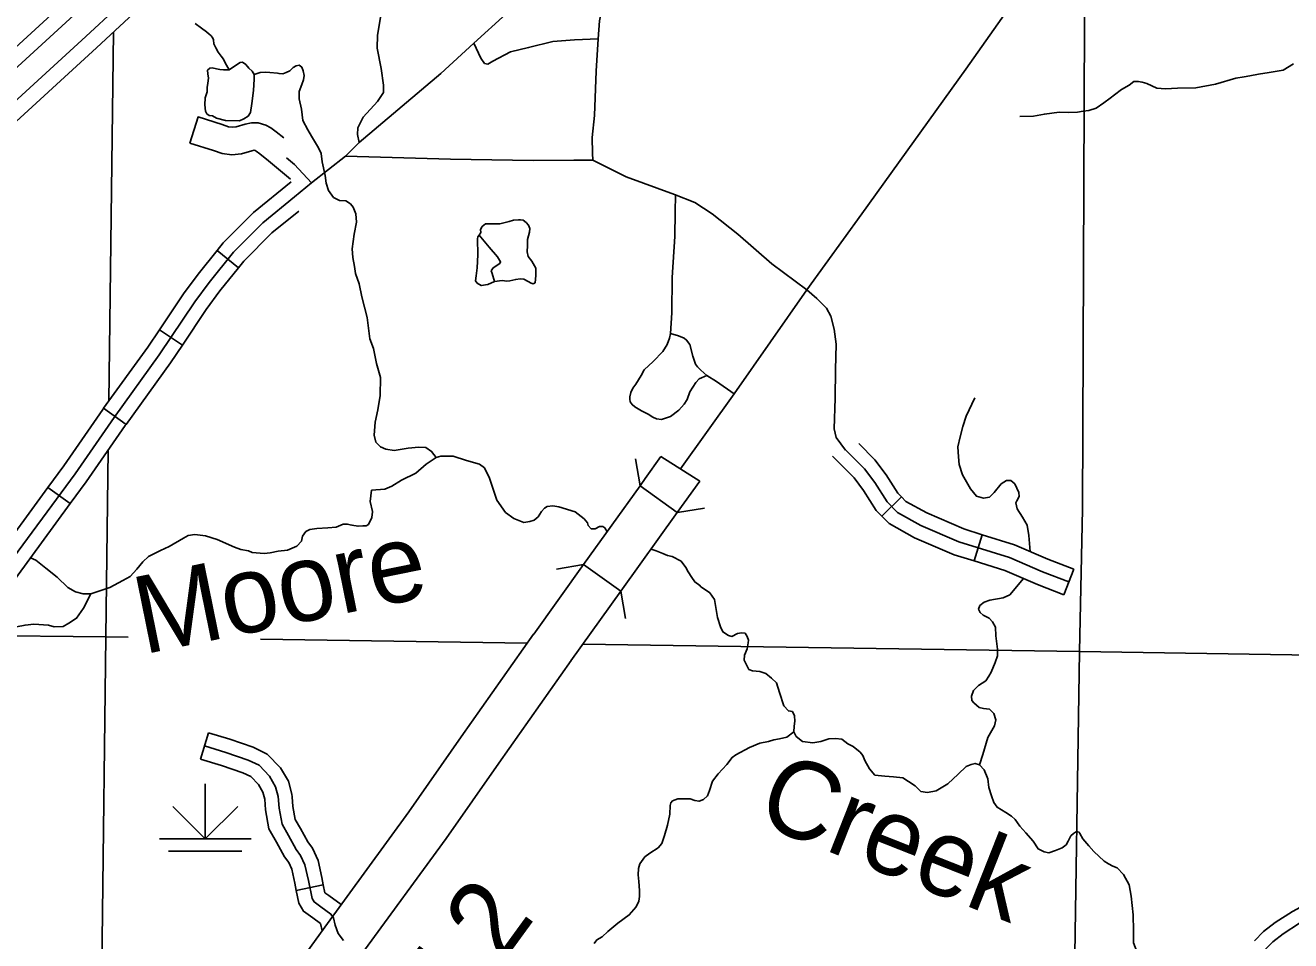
# Model space of a CAD drawing. Extents: x 8749 to 11879, y 13275 to 15339.
# Drawn here: x 9983.2 to 10121.1, y 13518.3 to 13618.1 of the extents above; entities that cross this region are included whole.
import ezdxf

# ---------------------------------------------------------------- set-up
doc = ezdxf.new("R2010")
doc.units = 0
for name, color, linetype in [('Level 15', 7, 'Continuous'), ('Level 19', 7, 'Continuous'), ('Level 32', 7, 'Continuous'), ('Level 35', 7, 'Continuous'), ('Level 37', 7, 'Continuous'), ('Level 44', 7, 'Continuous'), ('Level 45', 7, 'Continuous'), ('Level 46', 7, 'Continuous'), ('Level 48', 7, 'Continuous'), ('Level 5', 7, 'Continuous')]:
    doc.layers.add(name, color=color, linetype=linetype)

msp = doc.modelspace()

# ---------------------------------------------------------------- linework, layer by layer
at = {"layer": 'Level 15'}
msp.add_line((10056.71, 13568.38), (10052.47, 13571.05), dxfattribs=at)
for points in [[(10094.19, 13625.31), (10085.73, 13613.29), (10074.39, 13597.53), (10068.37, 13589.22), (10060.47, 13577.91), (10054.59, 13569.72)], [(9992.83, 13575.32), (9997.76, 13582.15), (10001.65, 13587.94), (10003.19, 13590.03), (10005.86, 13593.36), (10009.05, 13596.55), (10012.52, 13599.39)], [(9975.1, 13550.58), (9980.85, 13558.65), (9988.59, 13569.18), (9992.83, 13575.32)], [(10052.47, 13571.05), (10050.76, 13568.66), (10050.19, 13567.87)], [(10050.19, 13567.87), (10044.04, 13559.28)], [(10050.19, 13567.87), (10054.25, 13564.95)], [(10054.25, 13564.95), (10055.01, 13566.01), (10056.71, 13568.38)], [(10054.25, 13564.95), (10048.1, 13556.37)], [(10038.59, 13551.7), (10044.04, 13559.28)], [(10044.04, 13559.28), (10048.1, 13556.37)], [(10048.1, 13556.37), (10042.66, 13548.78)], [(9962.47, 13445.33), (9970.38, 13456.2), (9982.57, 13473.43), (9990.59, 13484.49), (9999.86, 13497.38), (10005.27, 13505.12), (10015.82, 13519.75), (10024.97, 13532.31), (10030.69, 13540.5), (10038.58, 13551.68)], [(9966.51, 13442.39), (9974.44, 13453.28), (9986.63, 13470.52), (9994.64, 13481.56), (10003.94, 13494.48), (10009.35, 13502.22), (10019.87, 13516.82), (10029.04, 13529.41), (10034.79, 13537.62), (10042.67, 13548.8)]]:
    msp.add_lwpolyline(points, dxfattribs=at)
at = {"layer": 'Level 19'}
for points in [[(9996.99, 13629.44), (9986.85, 13620.03), (9964.99, 13600.02), (9954.18, 13590.48), (9938.87, 13577.88), (9926.88, 13568.51), (9905.66, 13552.12), (9898.16, 13546.32), (9886.51, 13537.43), (9886.51, 13535.29)], [(9886.51, 13535.29), (9899.2, 13544.97), (9906.7, 13550.77), (9927.92, 13567.17), (9939.93, 13576.55), (9955.28, 13589.19), (9966.13, 13598.75), (9988, 13618.78), (9998.09, 13628.1)], [(9999.89, 13626.27), (9989.76, 13616.86), (9967.87, 13596.82), (9956.97, 13587.21), (9941.56, 13574.52), (9929.52, 13565.11), (9908.29, 13548.72), (9900.79, 13542.91), (9886.98, 13532.37)], [(9888.01, 13531.02), (9901.82, 13541.56), (9909.33, 13547.37), (9930.56, 13563.77), (9942.62, 13573.2), (9958.07, 13585.92), (9969, 13595.56), (9990.91, 13615.61), (10001.04, 13625.02)]]:
    msp.add_lwpolyline(points, dxfattribs=at)
at = {"layer": 'Level 32'}
for p, q in [((10006.41, 13591.65), (10004.06, 13593.52)), ((10000.28, 13583.21), (9997.79, 13584.88)), ((9994.14, 13574.56), (9991.7, 13576.32)), ((9988.05, 13565.92), (9985.63, 13567.69)), ((10078.69, 13566.65), (10076.54, 13564.57)), ((10087.51, 13562.53), (10086.62, 13559.67)), ((10097.48, 13558.79), (10096.4, 13555.99))]:
    msp.add_line(p, q, dxfattribs=at)
for points in [[(10032.08, 13616.12), (10035.59, 13619.32), (10038.64, 13621.69), (10041.86, 13624.58), (10046.36, 13628.25)], [(10045.04, 13603.37), (10045, 13604.12), (10044.98, 13605.84), (10045.21, 13608.25), (10045.42, 13613.07), (10045.63, 13616.6), (10045.78, 13618.55), (10046.07, 13619.95), (10046.53, 13621), (10047.66, 13622.57), (10047.91, 13622.98), (10047.95, 13623.59), (10047.89, 13624.68), (10047.64, 13625.91), (10047.1, 13627.25), (10046.36, 13628.25)], [(10018.06, 13603.81), (10019.55, 13605.31), (10028.45, 13612.83), (10032.08, 13616.12)], [(10032.08, 13616.12), (10032.82, 13614.48), (10033.24, 13613.93), (10033.6, 13613.85), (10034.13, 13614.18), (10036.06, 13615.17), (10038.03, 13615.65), (10040.69, 13616.3), (10043.04, 13616.51), (10045.63, 13616.6)], [(10012.52, 13599.39), (10014.37, 13600.9), (10018.06, 13603.81)], [(10068.37, 13589.22), (10064.57, 13592.08), (10060.87, 13595.31), (10058.05, 13597.54), (10056.15, 13598.75), (10053.94, 13599.63), (10048.66, 13601.57), (10045.04, 13603.37), (10042.98, 13603.37), (10038.53, 13603.34), (10029.53, 13603.48), (10018.06, 13603.81)], [(10004.06, 13593.52), (10004.74, 13594.37), (10008.04, 13597.67), (10012.13, 13601)], [(10053.5, 13584.47), (10053.67, 13586.72), (10053.69, 13590.57), (10053.99, 13595.04), (10054.01, 13597.72), (10054.05, 13599.58)], [(10006.41, 13591.65), (10006.98, 13592.36), (10010.05, 13595.44), (10012.97, 13597.82)], [(9997.79, 13584.88), (10000.42, 13588.8), (10002, 13590.94), (10004.06, 13593.52)], [(10000.28, 13583.21), (10002.88, 13587.08), (10004.38, 13589.11), (10006.41, 13591.65)], [(10071.46, 13577.43), (10071.5, 13580.51), (10071.56, 13583.31), (10071.35, 13584.93), (10071, 13586.35), (10070.52, 13587.23), (10069.47, 13588.3), (10068.37, 13589.22)], [(9991.7, 13576.32), (9996.53, 13583), (9997.79, 13584.88)], [(10057.46, 13579.88), (10056.65, 13579.54), (10056.27, 13579.12), (10055.62, 13578.12), (10055.32, 13577.26), (10055.01, 13576.76), (10054.42, 13576.13), (10053.5, 13575.42), (10052.52, 13575.11), (10051.98, 13575.15), (10051.6, 13575.36), (10051.08, 13575.69), (10050.36, 13576.03), (10049.61, 13576.47), (10049.32, 13576.72), (10049.13, 13577.03), (10049.07, 13577.33), (10049.07, 13577.58), (10049.17, 13578.04), (10049.42, 13578.52), (10049.74, 13578.94), (10050.3, 13579.9), (10050.64, 13580.51), (10051.62, 13581.41), (10052.69, 13582.5), (10053.15, 13583.28), (10053.4, 13583.97), (10053.5, 13584.47)], [(10060.47, 13577.91), (10058.54, 13579.25), (10057.46, 13579.88), (10056.81, 13580.49), (10056.45, 13580.83), (10056.24, 13581.14), (10055.93, 13582), (10055.61, 13583.26), (10055.26, 13583.76), (10055.01, 13583.95), (10054.4, 13584.22), (10053.5, 13584.47)], [(9994.14, 13574.56), (9999, 13581.29), (10000.28, 13583.21)], [(10071.46, 13577.43), (10071.37, 13574.07), (10071.56, 13573.12), (10072.61, 13571.76)], [(9985.63, 13567.69), (9987.37, 13570.05), (9991.61, 13576.19), (9991.7, 13576.32)], [(9988.05, 13565.92), (9989.81, 13568.31), (9994.06, 13574.45), (9994.14, 13574.56)], [(10078.69, 13566.65), (10078.31, 13567.05), (10077.04, 13569.06), (10075.81, 13570.7), (10074.03, 13572.48)], [(10076.54, 13564.57), (10075.94, 13565.19), (10074.57, 13567.35), (10073.54, 13568.72), (10071.17, 13571.1)], [(10096.94, 13557.39), (10094.08, 13558.49), (10090.49, 13560.03), (10084.96, 13561.75), (10080.79, 13563.55), (10078.26, 13564.94), (10077.13, 13566.12), (10075.81, 13568.21), (10074.67, 13569.71), (10072.62, 13571.76)], [(9979.37, 13559.16), (9979.64, 13559.53), (9985.63, 13567.69)], [(10087.51, 13562.53), (10085.48, 13563.16), (10081.45, 13564.9), (10079.18, 13566.15), (10078.69, 13566.65)], [(9981.82, 13557.42), (9982.07, 13557.77), (9988.05, 13565.92)], [(10086.62, 13559.67), (10084.44, 13560.35), (10080.13, 13562.2), (10077.34, 13563.74), (10076.54, 13564.57)], [(10097.48, 13558.79), (10094.65, 13559.88), (10091.02, 13561.44), (10087.51, 13562.53)], [(10096.4, 13555.99), (10093.52, 13557.1), (10089.97, 13558.62), (10086.62, 13559.67)], [(10126.39, 13524.18), (10125.74, 13523.81), (10123.07, 13522.39), (10121.33, 13521.46), (10119.44, 13520.23), (10118.19, 13519.26), (10117.21, 13518.26)]]:
    msp.add_lwpolyline(points, dxfattribs=at)
at = {"layer": 'Level 35'}
for points in [[(10005.4, 13613.22), (10005.1, 13613.73), (10004.92, 13614.07), (10004.78, 13614.39), (10004.52, 13614.71), (10004.17, 13615.16), (10003.95, 13615.61), (10003.7, 13616.07), (10003.67, 13616.5), (10003.56, 13616.76), (10003.38, 13616.95), (10003.19, 13617.13), (10002.9, 13617.36), (10002.36, 13617.78), (10001.69, 13618.28)], [(10004, 13607.95), (10004.98, 13607.71), (10006.53, 13607.67), (10007, 13607.87), (10007.47, 13608.18), (10007.72, 13608.57), (10007.87, 13609.55), (10008.04, 13610.98), (10008.13, 13612.19), (10008.11, 13612.73), (10007.9, 13613.07), (10007.53, 13613.42), (10007.2, 13613.81), (10006.85, 13614.07), (10006.57, 13614.02), (10005.96, 13613.62), (10005.4, 13613.22), (10004.76, 13613.21), (10004.37, 13613.27), (10003.99, 13613.34), (10003.52, 13613.44), (10003.28, 13613.39), (10003.03, 13613.17), (10003.05, 13612.79), (10003.14, 13612.31), (10003.06, 13611.76), (10002.98, 13611.28), (10002.98, 13610.82), (10002.78, 13610.17), (10002.75, 13609.4), (10002.82, 13608.73), (10002.94, 13608.44), (10003.22, 13608.24), (10003.56, 13608.22), (10004, 13607.95)], [(10013.3, 13613.53), (10013.02, 13613.73), (10012.71, 13613.67), (10012.37, 13613.47), (10012, 13613.13), (10011.6, 13612.93), (10011.25, 13612.79), (10010.83, 13612.82), (10010.65, 13612.87), (10009.83, 13612.95), (10009.38, 13612.98), (10008.78, 13612.92), (10008.11, 13612.73)], [(10027.96, 13570.94), (10027.46, 13571.62), (10026.84, 13572.03), (10026.05, 13572.08), (10024.92, 13571.97), (10023.39, 13571.73), (10022.47, 13571.87), (10021.9, 13572.11), (10021.39, 13572.62), (10021.2, 13573.38), (10021.31, 13574.81), (10021.58, 13576.16), (10021.85, 13577.7), (10021.88, 13579.67), (10021.44, 13581.21), (10021.12, 13582.83), (10020.72, 13583.89), (10020.42, 13586.23), (10019.85, 13588.47), (10019.58, 13589.9), (10019.18, 13591.02), (10019.05, 13591.78), (10018.88, 13592.75), (10018.8, 13593.72), (10019.02, 13595.29), (10019.26, 13596.61), (10019.21, 13597.53), (10018.91, 13598.26), (10018.61, 13598.63), (10018.1, 13598.93), (10017.4, 13598.99), (10016.78, 13599.32), (10016.22, 13600.07), (10015.95, 13600.86), (10015.84, 13601.72), (10015.54, 13603.2), (10015.43, 13604.1), (10015.11, 13604.72), (10014.36, 13605.98), (10013.95, 13606.69), (10013.41, 13607.71), (10013.28, 13608.95), (10013.01, 13610.06), (10013.01, 13610.86), (10013.3, 13611.64), (10013.49, 13612.15), (10013.55, 13612.61), (10013.47, 13613.12), (10013.3, 13613.53)], [(10110.79, 13611.26), (10112.93, 13611.67), (10115.14, 13612.31), (10116.05, 13612.45), (10116.7, 13612.58), (10117.64, 13612.75), (10118.78, 13612.93), (10120.31, 13613.2), (10121.44, 13613.88)], [(10091.6, 13608.13), (10093.11, 13608.18), (10094.29, 13608.4), (10095.91, 13608.59), (10096.91, 13608.56), (10097.9, 13608.62), (10098.5, 13608.7), (10099.12, 13608.78), (10099.93, 13609.05), (10100.76, 13609.64), (10101.44, 13610.15), (10101.92, 13610.51), (10102.7, 13611.07), (10103.54, 13611.56), (10104.05, 13611.94), (10104.51, 13611.96), (10104.94, 13611.88), (10105.45, 13611.72), (10106.56, 13611.23), (10107.5, 13611.15), (10108.79, 13611.21), (10110.79, 13611.26)], [(10032.48, 13594.8), (10032.5, 13595.01), (10032.65, 13595.18), (10032.84, 13595.47), (10032.79, 13595.81), (10032.96, 13596.13), (10033.34, 13596.42), (10033.68, 13596.44), (10034.18, 13596.42), (10034.89, 13596.44), (10035.92, 13596.69), (10036.38, 13596.84), (10036.95, 13596.86), (10037.16, 13596.86), (10037.43, 13596.82), (10037.77, 13596.59), (10038.04, 13596.29), (10038.17, 13595.92), (10038.12, 13595.54), (10037.91, 13594.74), (10037.91, 13594.07), (10037.89, 13593.37), (10037.98, 13592.87), (10038.38, 13592.37), (10038.82, 13591.61), (10038.82, 13590.79), (10038.75, 13590.01), (10038.54, 13589.89), (10038.31, 13589.97), (10037.98, 13590.16), (10037.52, 13590.39), (10037.1, 13590.43), (10036.63, 13590.37), (10036, 13590.22), (10035.65, 13590.18), (10035.17, 13590.24), (10034.31, 13590.16)], [(10032.48, 13594.8), (10032.5, 13593.06), (10032.44, 13591.65), (10032.33, 13590.75), (10032.25, 13590.22), (10032.42, 13589.97), (10032.88, 13589.7), (10033.59, 13589.82), (10034.31, 13590.16)], [(10032.65, 13595.18), (10033.74, 13593.9), (10034.66, 13592.83), (10034.98, 13592.3), (10034.89, 13592.11), (10034.18, 13591.63), (10033.97, 13591.32), (10034.05, 13591), (10034.31, 13590.16)], [(10092.72, 13560.71), (10092.57, 13562.46), (10092.39, 13563.59), (10091.9, 13564.45), (10091.33, 13565.37), (10091.17, 13566.02), (10091.28, 13566.24), (10091.52, 13566.69), (10091.5, 13567.13), (10091.04, 13568.07), (10090.61, 13568.45), (10090.15, 13568.45), (10089.58, 13568.07), (10088.8, 13567.15), (10088.29, 13566.61), (10087.64, 13566.53), (10086.86, 13566.75), (10086.21, 13567.53), (10085.35, 13569.07), (10085, 13570.2), (10084.92, 13571.03), (10084.84, 13572.13), (10085.11, 13573.21), (10085.4, 13574.32), (10085.75, 13575.45), (10086.7, 13577.45)], [(10020.9, 13567.39), (10022.35, 13567.49), (10023.14, 13567.84), (10024.16, 13568.49), (10025.75, 13569.24), (10026.88, 13570.22), (10027.96, 13570.94), (10028.47, 13571.08), (10028.98, 13571.11), (10029.82, 13571.08), (10031.28, 13570.62), (10032.68, 13570.24), (10033.24, 13569.82), (10033.78, 13568.69), (10034.59, 13566.31), (10035.53, 13564.96), (10036.42, 13564.29), (10037.5, 13563.86), (10038.17, 13563.96), (10038.63, 13564.13), (10039.08, 13564.49), (10039.46, 13565.05), (10039.76, 13565.43), (10040.06, 13565.61), (10040.68, 13565.69), (10041.35, 13565.58), (10043.1, 13565.02), (10044.1, 13564.26), (10044.45, 13563.81), (10044.55, 13563.52), (10044.85, 13563.19), (10045.31, 13563.17), (10045.77, 13563.43), (10046.14, 13563.41), (10046.36, 13563.27), (10046.59, 13562.84)], [(10020.57, 13563.66), (10020.93, 13564.4), (10021.03, 13565.04), (10021.03, 13565.07), (10020.76, 13566.15), (10020.9, 13567.39)], [(10016.16, 13563.27), (10017.04, 13563.37), (10017.8, 13563.67), (10018.26, 13563.69), (10018.77, 13563.59), (10019.44, 13563.45), (10019.95, 13563.5), (10020.33, 13563.5), (10020.57, 13563.66)], [(9993.79, 13557.55), (9994.6, 13557.98), (9995.3, 13558.79), (9995.98, 13559.58), (9996.6, 13560.14), (9997.89, 13560.82), (9998.83, 13561.25), (10000.42, 13562.17), (10000.91, 13562.44), (10001.66, 13562.54), (10002.82, 13562.41), (10004.06, 13562), (10005.95, 13561.17), (10006.65, 13560.93), (10007.49, 13560.79), (10007.91, 13560.6), (10009.21, 13560.49), (10009.85, 13560.57), (10010.74, 13560.74), (10011.74, 13560.84), (10012.76, 13561.28), (10013.28, 13561.84), (10013.38, 13562.38), (10013.73, 13562.87), (10014.19, 13563.11), (10014.95, 13563.22), (10016.16, 13563.27)], [(10062.07, 13547.84), (10061.53, 13548.86), (10061.59, 13549.4), (10061.88, 13550.1), (10061.99, 13550.73), (10062.02, 13551.05), (10061.86, 13551.45), (10061.64, 13551.78), (10061.26, 13551.83), (10060.81, 13551.75), (10060.19, 13551.45), (10059.84, 13551.56), (10059.22, 13551.94), (10058.95, 13552.48), (10058.65, 13553.5), (10058.46, 13554.58), (10058.3, 13555.45), (10057.81, 13556.18), (10057.33, 13556.53), (10056.82, 13556.85), (10056.71, 13557.01), (10056.17, 13557.39), (10055.85, 13557.88), (10055.44, 13558.5), (10055.17, 13558.96), (10054.66, 13559.66), (10053.69, 13560.14), (10053.2, 13560.25), (10052.67, 13560.47), (10051.96, 13560.79), (10051.39, 13560.97)], [(9984.3, 13559.77), (9983.71, 13560.01)], [(9993.79, 13557.55), (9992.36, 13556.77), (9991.17, 13556.39), (9990.31, 13556.07), (9989.47, 13556.1), (9988.64, 13556.29), (9987.8, 13556.77), (9986.62, 13557.9), (9985.4, 13558.88), (9984.3, 13559.77)], [(10090.5, 13555.96), (10091.99, 13557.76)], [(9979.21, 13549.09), (9979.91, 13550.44), (9981.18, 13551.68), (9982.2, 13552.49), (9983.14, 13552.68), (9984.09, 13552.76), (9985.68, 13552.68), (9986.3, 13552.49), (9987.29, 13552.54), (9987.91, 13552.87), (9988.75, 13553.43), (9989.5, 13554.54), (9990.31, 13556.07)], [(10087.19, 13537.43), (10087.56, 13538.58), (10088.13, 13540.42), (10088.83, 13541.69), (10088.99, 13542.36), (10088.77, 13543.04), (10088.29, 13543.5), (10087.64, 13543.6), (10087.18, 13543.68), (10086.59, 13544.2), (10086.37, 13544.47), (10086.32, 13544.94), (10086.54, 13545.56), (10087.08, 13546.1), (10087.91, 13546.61), (10088.23, 13547.12), (10088.48, 13547.55), (10088.91, 13548.58), (10089.15, 13549.31), (10089.18, 13550.06), (10088.99, 13551.52), (10088.94, 13552.44), (10088.64, 13553.05), (10088.26, 13553.45), (10087.61, 13553.75), (10087.26, 13554.05), (10087.1, 13554.42), (10087.24, 13554.8), (10087.7, 13555.18), (10088.34, 13555.4), (10089.8, 13555.64), (10090.5, 13555.96)], [(10062.07, 13547.84), (10062.46, 13547.69), (10063.27, 13547.63), (10063.92, 13547.39), (10064.54, 13546.88), (10065.08, 13546.39), (10065.4, 13545.31), (10065.88, 13543.88), (10066.37, 13543.32), (10066.8, 13543.26), (10067.02, 13542.8), (10067.07, 13542.21), (10066.99, 13541.64), (10066.96, 13541.05), (10067.23, 13540.54), (10067.91, 13540), (10069.04, 13539.83), (10069.9, 13539.97)], [(10066.96, 13541.05), (10066.19, 13540.46), (10065.38, 13540.28), (10064.79, 13540.17), (10064.19, 13539.98), (10063.25, 13539.79), (10062.12, 13539.33), (10060.63, 13538.52), (10060.23, 13538.25), (10059.64, 13537.47), (10058.72, 13536.44), (10058.1, 13535.66), (10057.75, 13534.63), (10057.53, 13534.07), (10057.1, 13533.66), (10056.62, 13533.47), (10056.16, 13533.55), (10055.67, 13533.72), (10055.11, 13533.74), (10054.32, 13533.74), (10053.73, 13533.5), (10053.54, 13533.28), (10053.49, 13532.99)], [(10069.9, 13539.97), (10070.77, 13540.26), (10071.5, 13540.32), (10072.2, 13540.24), (10072.85, 13539.72), (10073.44, 13539.43), (10074.2, 13538.81), (10074.47, 13538.46), (10074.71, 13537.92), (10075.22, 13537), (10075.81, 13536.32), (10076.89, 13536.19), (10077.81, 13536.14), (10078.83, 13536.03), (10079.48, 13535.62), (10080.18, 13535.16), (10080.8, 13534.54), (10081.55, 13534.44), (10082.47, 13534.62), (10083.74, 13535.38), (10084.87, 13536.41), (10085.76, 13537.24), (10086.3, 13537.48), (10086.73, 13537.59), (10087.19, 13537.43), (10087.72, 13536.89), (10088.13, 13535.92), (10088.23, 13534.98), (10088.5, 13534.06), (10088.75, 13533.33), (10089.12, 13532.82), (10090.07, 13532.25), (10090.71, 13531.84), (10091.09, 13531.49), (10091.6, 13530.74), (10092.25, 13530.04), (10093.06, 13529.13), (10093.6, 13528.29), (10094.24, 13527.97), (10094.76, 13527.86), (10095.48, 13528.08), (10096.21, 13528.4), (10096.64, 13528.7), (10096.89, 13529.13), (10097.18, 13529.69), (10097.45, 13529.96), (10097.78, 13530.18), (10098.07, 13530.1), (10098.15, 13529.94), (10098.48, 13529.37), (10099.12, 13528.61), (10099.69, 13527.99)], [(10053.49, 13532.99), (10053.44, 13532.06), (10053.17, 13530.87), (10052.87, 13529.74), (10052.58, 13528.87), (10052.17, 13528.39), (10051.25, 13527.79), (10050.72, 13527.39), (10050.15, 13526.66), (10050.01, 13526.12), (10049.99, 13525.45), (10050.07, 13524.72), (10050.12, 13523.72), (10050.12, 13523.07), (10050.07, 13522.58), (10049.77, 13521.96), (10049.02, 13521.07), (10047.75, 13520.16)], [(10106.77, 13512.25), (10105.81, 13513.11), (10105.22, 13514.41), (10105.01, 13515.81), (10104.44, 13516.92), (10104.01, 13518.02), (10103.98, 13519.32), (10103.95, 13521.1), (10103.74, 13523.1), (10103.52, 13524.37), (10102.9, 13525.49), (10102.23, 13526.19), (10101.74, 13526.4), (10101.26, 13526.65), (10100.8, 13526.94), (10099.69, 13527.99)], [(10045.19, 13517.95), (10045.49, 13518.36), (10046.05, 13518.68), (10046.67, 13519.25), (10047.75, 13520.16)]]:
    msp.add_lwpolyline(points, dxfattribs=at)
at = {"layer": 'Level 37'}
for points in [[(10050.19, 13567.86), (10049.7, 13570.82)], [(10057.22, 13565.44), (10054.26, 13564.95)], [(10041.08, 13558.79), (10044.04, 13559.28)], [(10048.11, 13556.37), (10048.59, 13553.41)]]:
    msp.add_lwpolyline(points, dxfattribs=at)
at = {"layer": 'Level 44'}
for p, q in [((10002.78, 13535.38), (10002.78, 13529.38)), ((10002.78, 13529.38), (9999.25, 13532.91)), ((10002.78, 13529.38), (10006.32, 13532.91)), ((9997.78, 13529.38), (10007.78, 13529.38)), ((9998.78, 13528.01), (10006.78, 13528.01))]:
    msp.add_line(p, q, dxfattribs=at)
at = {"layer": 'Level 45'}
for p, q in [((10002.25, 13538.06), (10003.12, 13540.93)), ((10012.71, 13523.73), (10015.65, 13524.34))]:
    msp.add_line(p, q, dxfattribs=at)
for points in [[(10019.55, 13605.31), (10019.37, 13606.19), (10019.41, 13606.89), (10019.99, 13608.06), (10021.57, 13609.78), (10022.23, 13610.77), (10022.23, 13611.54), (10021.97, 13613.38), (10021.53, 13615.58), (10021.57, 13617.01), (10022.23, 13620.89), (10022.48, 13622.32), (10023.29, 13623.68), (10025.12, 13625.62), (10026.8, 13626.98), (10027.27, 13627.48), (10027.9, 13628.22), (10028.44, 13627.87)], [(10003.12, 13540.93), (10005.47, 13540.22), (10008.02, 13539.36), (10009.54, 13538.62), (10010.99, 13537.12), (10011.84, 13535.64), (10012.22, 13534.25), (10012.25, 13533.96)], [(10002.68, 13539.5), (10005.01, 13538.79), (10007.45, 13537.96), (10008.65, 13537.39), (10009.78, 13536.21), (10010.44, 13535.05), (10010.74, 13533.98), (10010.85, 13532.72), (10011.15, 13530.96), (10011.85, 13529.74), (10012.69, 13528.22), (10013.18, 13527.57), (10013.65, 13526.52), (10014.02, 13524.83), (10014.42, 13522.88), (10014.64, 13522.5), (10015.38, 13521.96), (10016.48, 13521.17), (10016.75, 13520.76), (10016.93, 13519.95), (10017.29, 13519.03), (10017.85, 13518.29)], [(10002.25, 13538.06), (10004.56, 13537.36), (10006.88, 13536.57), (10007.75, 13536.15), (10008.57, 13535.3), (10009.05, 13534.47), (10009.26, 13533.71), (10009.26, 13533.71)], [(10009.26, 13533.71), (10009.36, 13532.53), (10009.72, 13530.45), (10010.55, 13529.01), (10011.43, 13527.4), (10011.88, 13526.8), (10012.22, 13526.05), (10012.55, 13524.52), (10012.71, 13523.73)], [(10012.25, 13533.96), (10012.34, 13532.91), (10012.58, 13531.48), (10013.16, 13530.48), (10013.95, 13529.04), (10014.48, 13528.35), (10015.09, 13526.99), (10015.48, 13525.14), (10015.65, 13524.34)], [(10012.71, 13523.73), (10013, 13522.36), (10013.49, 13521.48), (10014.51, 13520.75), (10015.35, 13520.13), (10015.52, 13519.34)], [(10015.65, 13524.34), (10015.83, 13523.49), (10016.26, 13523.18), (10017.61, 13522.2)]]:
    msp.add_lwpolyline(points, dxfattribs=at)
at = {"layer": 'Level 46'}
for points in [[(10011.33, 13605.82), (10010.52, 13606.48), (10009.94, 13606.89), (10009.4, 13607.19), (10008.55, 13607.45), (10007.83, 13607.45), (10007.12, 13607.3), (10006.14, 13607.01), (10005.71, 13606.96), (10005.33, 13607.02), (10004.61, 13607.27), (10001.99, 13608.09), (10001.09, 13605.23)], [(10001.09, 13605.23), (10003.66, 13604.42), (10004.61, 13604.09), (10005.66, 13603.94), (10006.74, 13604.06), (10007.85, 13604.39), (10008.12, 13604.45), (10008.21, 13604.42), (10008.34, 13604.34), (10008.72, 13604.08), (10009.69, 13603.29), (10012.06, 13601.32)], [(10014.37, 13600.9), (10012.51, 13602.89), (10011.62, 13603.63)], [(10163.26, 13544.72), (10161.96, 13544), (10151.35, 13537.91), (10146.61, 13535.22), (10142.06, 13532.33), (10133.23, 13526.58), (10129.49, 13524.21), (10126.46, 13522.49), (10123.78, 13521.07), (10122.09, 13520.16), (10120.31, 13519.01), (10119.19, 13518.13), (10117.16, 13516.07), (10115.66, 13514.6), (10114.8, 13513.81), (10113.83, 13513.12), (10112.83, 13512.65)]]:
    msp.add_lwpolyline(points, dxfattribs=at)
at = {"layer": 'Level 5'}
for points in [[(10098.69, 13627.31), (10098.42, 13565.32), (10098.11, 13549.79)], [(9992.76, 13617.33), (9992.27, 13577.1)], [(9992.2, 13571.77), (9991.95, 13551.38)], [(9991.95, 13551.38), (9977.62, 13551.53)], [(9991.95, 13551.38), (9991.14, 13485.26)], [(9994.38, 13551.35), (9991.95, 13551.38)], [(10037.89, 13550.7), (10008.79, 13551.13)], [(10098.11, 13549.79), (10043.96, 13550.6)], [(10098.11, 13549.79), (10097.5, 13509.67)], [(10165.21, 13548.74), (10098.11, 13549.79)]]:
    msp.add_lwpolyline(points, dxfattribs=at)

# ---------------------------------------------------------------- texts
at = {"layer": 'Level 35'}
for s, rotation, p in [('Moore', 11.4934, (9996.03, 13549.47)), ('Creek', 338.4787, (10062.58, 13531.2))]:
    msp.add_text(s, height=8.448, rotation=rotation, dxfattribs=at).set_placement(p)
at = {"layer": 'Level 48'}
msp.add_text('7.2', height=8.448, rotation=53.9415, dxfattribs=at).set_placement((10029.59, 13508.11))

doc.saveas('drawing.dxf')
